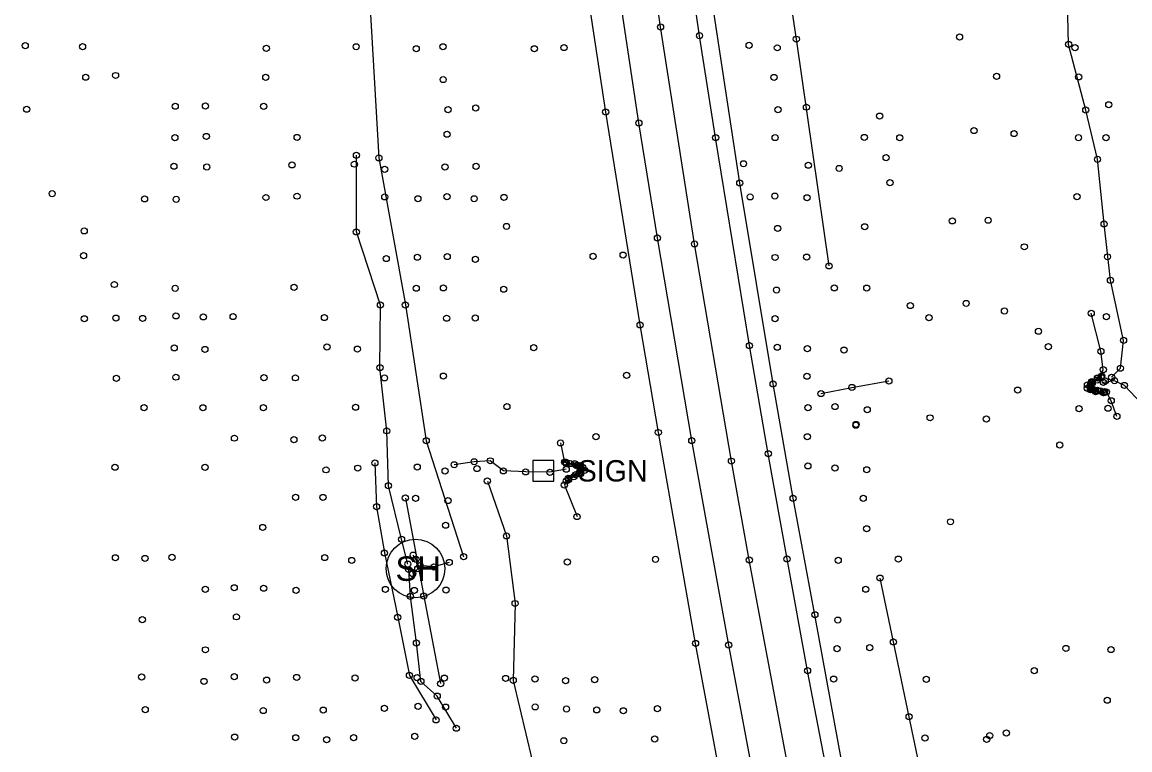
# Model space of a CAD drawing. Extents: x 20503438 to 20508873, y 7964251 to 7984667.
# Drawn here: x 20505289.4 to 20505651.7, y 7977511.9 to 7977750 of the extents above; entities that cross this region are included whole.
import ezdxf

# ---------------------------------------------------------------- set-up
doc = ezdxf.new("R2010")
doc.units = 0
for name, color, linetype in [('SurBreakLine', 7, 'Continuous'), ('SurConcreteSlab', 7, 'Continuous'), ('SurDikeDam', 7, 'Continuous'), ('SurDrainageArrowDown', 7, 'Continuous'), ('SurDrainageArrowUp', 7, 'Continuous'), ('SurEdgeRoadPaved', 7, 'Continuous'), ('SurEdgeShoulderPaved', 7, 'Continuous'), ('SurFenceWire', 7, 'Continuous'), ('SurNaturalCells', 7, 'Continuous'), ('SurPointsNonDTM', 7, 'Continuous'), ('SurRoadPoints', 7, 'Continuous'), ('SurSurveyPoints', 7, 'Continuous')]:
    doc.layers.add(name, color=color, linetype=linetype)

msp = doc.modelspace()

# ---------------------------------------------------------------- linework, layer by layer
at = {"layer": 'SurBreakLine'}
for points in [[(20505621, 7977152.86), (20505604.98, 7977215.01), (20505590.31, 7977274.51), (20505563.53, 7977392.87), (20505556.63, 7977425.21), (20505550.12, 7977454.94), (20505544.87, 7977479.94), (20505527.25, 7977573.99), (20505521.39, 7977606.33), (20505509.32, 7977677.42), (20505498.21, 7977748.43), (20505483.28, 7977852.68), (20505478.77, 7977888.4), (20505466.7, 7977991.92), (20505463.05, 7978027.55)], [(20505647.47, 7977620.99), (20505645.62, 7977626.09), (20505644.06, 7977628.96), (20505643.01, 7977628.73), (20505640.51, 7977629.08), (20505638.82, 7977629.74), (20505637.81, 7977630.2), (20505637.84, 7977631.3), (20505639.26, 7977632.34), (20505641.12, 7977633.5), (20505642.49, 7977634.2), (20505643.03, 7977636.27), (20505642.26, 7977642.28), (20505639.09, 7977654.7)], [(20505465.49, 7977612.31), (20505466.84, 7977606.05), (20505467.31, 7977605.99), (20505470.16, 7977605.47), (20505472.04, 7977604.9), (20505472.78, 7977604.33), (20505473.39, 7977603.28), (20505472.04, 7977602.24), (20505468.21, 7977600.3), (20505467.4, 7977599.82), (20505466.76, 7977598.5), (20505470.9, 7977588.19)], [(20505404.8, 7977605.75), (20505405.32, 7977591.43), (20505407.9, 7977576.32), (20505412.25, 7977555.25), (20505416.09, 7977536.21), (20505424.81, 7977521.66)], [(20505417.14, 7977569.55), (20505418.82, 7977571.12), (20505418.23, 7977574.18), (20505417.3, 7977575.6)], [(20505429.11, 7977573.2), (20505424.11, 7977571.71), (20505419.51, 7977572.18)]]:
    msp.add_lwpolyline(points, dxfattribs=at)
at = {"layer": 'SurConcreteSlab'}
for points in [[(20505643.39, 7977629.05), (20505643.23, 7977628.73), (20505640.36, 7977629.38), (20505639.46, 7977629.72), (20505638.96, 7977630.23), (20505638.77, 7977630.71), (20505638.85, 7977631.5), (20505639.32, 7977632.11), (20505642.33, 7977633.87), (20505642.48, 7977633.61), (20505641.03, 7977632.86), (20505639.43, 7977631.95), (20505639.01, 7977631.33), (20505638.99, 7977631.06), (20505639.01, 7977630.36), (20505639.67, 7977629.84), (20505641.1, 7977629.49), (20505642.12, 7977629.27)], [(20505467.42, 7977605.48), (20505470.56, 7977604.91), (20505471.47, 7977604.61), (20505471.85, 7977604.25), (20505472.06, 7977603.44), (20505471.76, 7977602.7), (20505470.5, 7977601.95), (20505468.03, 7977600.74), (20505468.21, 7977600.4), (20505469.86, 7977601.22), (20505471.5, 7977602.34), (20505472.03, 7977602.74), (20505472.16, 7977603.41), (20505472.05, 7977604.07), (20505471.79, 7977604.59), (20505471.13, 7977604.99), (20505468.69, 7977605.54), (20505467.33, 7977605.79)]]:
    msp.add_lwpolyline(points, close=True, dxfattribs=at)
at = {"layer": 'SurDikeDam'}
msp.add_lwpolyline([(20505550.69, 7977628.45), (20505560.79, 7977630.46), (20505572.91, 7977632.56)], dxfattribs=at)
at = {"layer": 'SurDrainageArrowDown'}
for points in [[(20505397.06, 7977881.61), (20505401.42, 7977854.15), (20505399.21, 7977831.29), (20505394.68, 7977816.75), (20505398.07, 7977791.52), (20505403.18, 7977756.31), (20505406.08, 7977705.57), (20505414.75, 7977657.44), (20505421.59, 7977613), (20505433.78, 7977575.08)], [(20505748.21, 7977193.29), (20505742.63, 7977213.06), (20505736.52, 7977234.9), (20505725.99, 7977280.52), (20505713.88, 7977327.5), (20505706.79, 7977347.37), (20505703.26, 7977372.92), (20505698.22, 7977399.33), (20505687.89, 7977446.43), (20505678.89, 7977496.64), (20505669.89, 7977547.69), (20505664.57, 7977573.19), (20505657.6, 7977599.18), (20505657.57, 7977623.02), (20505649.94, 7977631.12), (20505646.7, 7977632.62), (20505643.09, 7977632.08)], [(20505467.36, 7977603.7), (20505462.05, 7977602.69), (20505454.1, 7977602.82), (20505446.83, 7977603.14), (20505442.51, 7977606.44), (20505437.25, 7977606.12), (20505430.71, 7977605.14)], [(20505431.43, 7977518.95), (20505425.16, 7977529.46), (20505419.84, 7977534.25), (20505418.36, 7977546.85), (20505416.39, 7977562.07), (20505415.84, 7977570.88)], [(20505643.24, 7977229.57), (20505637.82, 7977253.97), (20505632.4, 7977278.37), (20505626.97, 7977302.78), (20505621.55, 7977327.18), (20505616.12, 7977351.59), (20505610.7, 7977375.99), (20505605.27, 7977400.4), (20505600.04, 7977424.84), (20505594.91, 7977449.31), (20505589.78, 7977473.78), (20505584.65, 7977498.25), (20505579.51, 7977522.71), (20505574.38, 7977547.18), (20505570, 7977568.06)]]:
    msp.add_lwpolyline(points, dxfattribs=at)
at = {"layer": 'SurDrainageArrowUp'}
for points in [[(20505474.88, 7978262.46), (20505478.99, 7978261.36), (20505482.21, 7978256.52), (20505486.17, 7978242.38), (20505487.91, 7978215.78), (20505489.93, 7978188.71), (20505495.31, 7978138.74), (20505498.58, 7978086.73), (20505503.22, 7978036.77), (20505509.44, 7977986.63), (20505514.32, 7977937.98), (20505520.92, 7977890), (20505527.82, 7977841.73), (20505542.62, 7977744.41), (20505553.31, 7977670.21)], [(20505645.76, 7977633.8), (20505648.64, 7977636.75), (20505649.66, 7977645.85), (20505645.38, 7977665.53), (20505643.3, 7977683.97), (20505641.13, 7977705.1), (20505637.29, 7977721.21), (20505631.69, 7977742.67), (20505631.11, 7977766.07), (20505627.11, 7977793.04), (20505625.06, 7977817.31), (20505619.53, 7977842.17), (20505617.3, 7977864.92), (20505613.95, 7977892.53), (20505608.5, 7977918.86), (20505604.09, 7977945.74), (20505602.24, 7977974.48), (20505599.16, 7977998.23)], [(20505415.56, 7977572.66), (20505413.52, 7977580.76), (20505409.22, 7977598.28), (20505408.68, 7977616.25), (20505406.45, 7977636.92), (20505406.61, 7977657.41), (20505398.72, 7977681.34), (20505398.75, 7977706.42)], [(20505441.58, 7977599.83), (20505447.83, 7977581.87), (20505450.65, 7977559.76), (20505450.04, 7977534.57), (20505456.22, 7977508.44), (20505457.64, 7977486.03), (20505466.52, 7977459.64), (20505477.85, 7977428.39), (20505482.66, 7977408.47), (20505486.85, 7977381.17), (20505484.36, 7977356.21), (20505484.49, 7977331.46), (20505490.08, 7977296.7), (20505493.03, 7977278)]]:
    msp.add_lwpolyline(points, dxfattribs=at)
at = {"layer": 'SurEdgeRoadPaved'}
for points in [[(20505624.63, 7977187.2), (20505615.58, 7977223), (20505606.62, 7977259.66), (20505597.81, 7977296.68), (20505589.63, 7977332.14), (20505573.81, 7977402.79), (20505559.4, 7977470.78), (20505552.63, 7977504.94), (20505546.29, 7977537.77), (20505539.58, 7977574.35), (20505533.46, 7977608.75), (20505527.3, 7977644.15), (20505516.24, 7977712.18), (20505510.96, 7977745.54), (20505501.31, 7977811.8), (20505496.38, 7977847.32), (20505492.39, 7977879.09), (20505484.78, 7977942.17), (20505477.37, 7978006.84)], [(20505601.04, 7977184.16), (20505592.64, 7977217.57), (20505583.13, 7977256.03), (20505574.67, 7977291.27), (20505566.25, 7977327.77), (20505557.96, 7977364.71), (20505543.09, 7977432.36), (20505534.48, 7977473.22), (20505527.49, 7977508.89), (20505520.5, 7977546.16), (20505508.44, 7977613.06), (20505497.19, 7977679.37), (20505491.12, 7977717.01), (20505485.69, 7977753.34), (20505476.1, 7977820.74), (20505471.46, 7977854.08), (20505467.12, 7977888.06), (20505463.18, 7977920.65), (20505454.58, 7977996.31)]]:
    msp.add_lwpolyline(points, dxfattribs=at)
at = {"layer": 'SurEdgeShoulderPaved'}
for points in [[(20505601.72, 7977139.15), (20505583.71, 7977209.07), (20505575.33, 7977242.93), (20505565.57, 7977283.29), (20505550.94, 7977346.79), (20505536.84, 7977411.29), (20505530.41, 7977441.51), (20505522.43, 7977478.43), (20505509.67, 7977546.7), (20505497.51, 7977615.71), (20505491.52, 7977650.91), (20505480.28, 7977720.53), (20505474.86, 7977756.43), (20505470.13, 7977789.88), (20505464.4, 7977828.65), (20505459.75, 7977863.94), (20505455.67, 7977897.35), (20505450.99, 7977936.46), (20505443.13, 7978005.6)], [(20505641.05, 7977146.39), (20505623.31, 7977215.43), (20505614.62, 7977249.64), (20505606.42, 7977284.19), (20505597.79, 7977321.49), (20505583.89, 7977382.89), (20505576.25, 7977417.57), (20505568.92, 7977452.29), (20505561.28, 7977487.06), (20505548.69, 7977556.07), (20505541.57, 7977594.18), (20505535.02, 7977631.59), (20505524.12, 7977697.3), (20505514.01, 7977764.14), (20505504.07, 7977833.33), (20505499.51, 7977867.01), (20505491.05, 7977936.71), (20505486.93, 7977972.52), (20505483.11, 7978007.2)]]:
    msp.add_lwpolyline(points, dxfattribs=at)
at = {"layer": 'SurFenceWire'}
msp.add_lwpolyline([(20505414.75, 7977594.26), (20505420.77, 7977562.17), (20505426.29, 7977533.54)], dxfattribs=at)
at = {"layer": 'SurNaturalCells'}
msp.add_circle((20505418.04, 7977571.17), 9.59, dxfattribs=at)
at = {"layer": 'SurPointsNonDTM'}
for centre in [(20505562.17, 7977618.34), (20505414.75, 7977594.26), (20505420.77, 7977562.17), (20505426.29, 7977533.54)]:
    msp.add_circle(centre, 1, dxfattribs=at)
at = {"layer": 'SurRoadPoints'}
msp.add_lwpolyline([(20505459.91, 7977599.74), (20505459.91, 7977599.74), (20505463.34, 7977599.74), (20505463.34, 7977606.6), (20505456.48, 7977606.6), (20505456.48, 7977599.74), (20505459.91, 7977599.74)], dxfattribs=at)
at = {"layer": 'SurSurveyPoints'}
for centre in [(20505498.21, 7977748.43), (20505290.41, 7977742.28), (20505510.96, 7977745.54), (20505527.18, 7977742.37), (20505542.62, 7977744.41), (20505596.02, 7977745.1), (20505631.69, 7977742.67), (20505309.18, 7977741.94), (20505369.29, 7977741.4), (20505398.66, 7977741.93), (20505418.32, 7977741.25), (20505427.06, 7977741.92), (20505456.95, 7977741.25), (20505466.64, 7977741.65), (20505536.37, 7977741.57), (20505633.78, 7977741.62), (20505310.21, 7977731.94), (20505319.97, 7977732.52), (20505369.1, 7977731.92), (20505535.34, 7977731.89), (20505608.11, 7977732.23), (20505634.99, 7977732.07), (20505427.12, 7977731.19), (20505290.9, 7977721.47), (20505339.48, 7977722.47), (20505349.35, 7977722.54), (20505368.41, 7977722.41), (20505428.7, 7977721.32), (20505437.79, 7977721.89), (20505480.28, 7977720.53), (20505536.63, 7977721.32), (20505545.93, 7977722.15), (20505637.29, 7977721.21), (20505644.82, 7977722.95), (20505491.12, 7977717.01), (20505569.88, 7977719.22), (20505428.4, 7977713.29), (20505600.73, 7977714.49), (20505613.86, 7977713.51), (20505339.38, 7977712.16), (20505349.67, 7977712.58), (20505379.34, 7977712.24), (20505516.24, 7977712.18), (20505535.7, 7977712.22), (20505564.86, 7977712.24), (20505576.47, 7977712.14), (20505634.92, 7977712.16), (20505643.93, 7977712.19), (20505398.75, 7977706.42), (20505339.03, 7977702.82), (20505349.81, 7977702.56), (20505377.67, 7977703.26), (20505398.07, 7977703.5), (20505406.08, 7977705.57), (20505427.71, 7977702.57), (20505437.9, 7977702.78), (20505525.35, 7977703.63), (20505546.55, 7977703.16), (20505571.99, 7977705.62), (20505641.13, 7977705.1), (20505408.01, 7977701.83), (20505556.64, 7977702.12), (20505524.12, 7977697.3), (20505573.26, 7977697.46), (20505299.23, 7977693.86), (20505329.44, 7977692.13), (20505339.78, 7977691.99), (20505369.14, 7977692.6), (20505379.32, 7977693.03), (20505408.01, 7977692.81), (20505418.86, 7977692.18), (20505428.36, 7977692.87), (20505437.26, 7977692.19), (20505447, 7977692.62), (20505527.53, 7977692.81), (20505535.6, 7977693.05), (20505546.15, 7977692.5), (20505634.43, 7977692.86), (20505593.67, 7977684.94), (20505605.37, 7977685.15), (20505309.7, 7977681.67), (20505398.72, 7977681.34), (20505447.83, 7977683.14), (20505536.53, 7977682.48), (20505564.98, 7977683.02), (20505643.3, 7977683.97), (20505497.19, 7977679.37), (20505509.32, 7977677.42), (20505309.49, 7977673.58), (20505485.98, 7977673.74), (20505617.19, 7977676.46), (20505408.49, 7977672.62), (20505418.69, 7977673.04), (20505428.45, 7977673.28), (20505437.68, 7977672.36), (20505476.15, 7977673.33), (20505535.68, 7977672.97), (20505546.02, 7977673.11), (20505553.31, 7977670.21), (20505644.41, 7977673.19), (20505319.57, 7977664.13), (20505339.46, 7977662.87), (20505378.37, 7977663.22), (20505418.31, 7977662.9), (20505427.2, 7977663.02), (20505446.93, 7977662.58), (20505555.05, 7977663.01), (20505565.67, 7977662.95), (20505645.38, 7977665.53), (20505536.14, 7977662.3), (20505406.61, 7977657.41), (20505414.75, 7977657.44), (20505579.9, 7977657.23), (20505598.18, 7977657.94), (20505610.71, 7977655.46), (20505309.76, 7977652.93), (20505320.07, 7977653.14), (20505328.82, 7977653.02), (20505339.73, 7977653.87), (20505348.66, 7977653.54), (20505358.4, 7977653.65), (20505388.29, 7977653.32), (20505428.26, 7977653.11), (20505437.6, 7977653.17), (20505535.69, 7977652.94), (20505586.02, 7977653.29), (20505639.09, 7977654.7), (20505644.06, 7977653.62), (20505491.52, 7977650.91), (20505621.83, 7977648.85), (20505649.66, 7977645.85), (20505339.15, 7977643.39), (20505349.19, 7977642.9), (20505389.11, 7977643.68), (20505399.07, 7977642.98), (20505456.75, 7977643.45), (20505527.3, 7977644.15), (20505536.37, 7977643.61), (20505546.23, 7977643.12), (20505558.21, 7977642.66), (20505625.07, 7977643.81), (20505642.26, 7977642.28), (20505339.7, 7977633.81), (20505368.5, 7977633.65), (20505378.79, 7977633.59), (20505406.45, 7977636.92), (20505407.93, 7977633.58), (20505427.19, 7977634.15), (20505487.13, 7977634.41), (20505546.11, 7977634.13), (20505642.33, 7977633.87), (20505642.48, 7977633.61), (20505642.49, 7977634.2), (20505643.03, 7977636.27), (20505645.76, 7977633.8), (20505648.64, 7977636.75), (20505320.26, 7977633.42), (20505535.02, 7977631.59), (20505560.79, 7977630.46), (20505572.91, 7977632.56), (20505637.81, 7977630.2), (20505637.84, 7977631.3), (20505638.77, 7977630.71), (20505638.85, 7977631.5), (20505638.96, 7977630.23), (20505638.99, 7977631.06), (20505639.01, 7977631.33), (20505639.01, 7977630.36), (20505639.26, 7977632.34), (20505639.32, 7977632.11), (20505639.43, 7977631.95), (20505641.03, 7977632.86), (20505641.12, 7977633.5), (20505643.09, 7977632.08), (20505643.66, 7977632.6), (20505646.7, 7977632.62), (20505649.94, 7977631.12), (20505550.69, 7977628.45), (20505615.01, 7977629.59), (20505638.82, 7977629.74), (20505639.46, 7977629.72), (20505639.67, 7977629.84), (20505640.36, 7977629.38), (20505640.51, 7977629.08), (20505641.1, 7977629.49), (20505642.12, 7977629.27), (20505643.01, 7977628.73), (20505643.23, 7977628.73), (20505643.39, 7977629.05), (20505644.06, 7977628.96), (20505329.3, 7977623.82), (20505348.54, 7977623.8), (20505368.32, 7977623.83), (20505398.47, 7977623.98), (20505447.96, 7977624.18), (20505546.43, 7977623.84), (20505555.29, 7977624.19), (20505565.82, 7977623.15), (20505635.12, 7977623.52), (20505644.56, 7977623.65), (20505645.62, 7977626.09), (20505586.37, 7977620.51), (20505604.78, 7977620.13), (20505647.47, 7977620.99), (20505408.68, 7977616.25), (20505497.51, 7977615.71), (20505562.09, 7977618.09), (20505358.85, 7977613.85), (20505378.29, 7977613.36), (20505387.58, 7977613.91), (20505421.59, 7977613), (20505465.49, 7977612.31), (20505477.1, 7977614.36), (20505508.44, 7977613.06), (20505546.21, 7977614.31), (20505533.46, 7977608.75), (20505628.78, 7977611.61), (20505404.8, 7977605.75), (20505430.71, 7977605.14), (20505437.25, 7977606.12), (20505442.51, 7977606.44), (20505466.84, 7977606.05), (20505467.31, 7977605.99), (20505467.33, 7977605.79), (20505467.42, 7977605.48), (20505468.69, 7977605.54), (20505470.16, 7977605.47), (20505470.56, 7977604.91), (20505471.13, 7977604.99), (20505471.47, 7977604.61), (20505471.79, 7977604.59), (20505472.04, 7977604.9), (20505521.39, 7977606.33), (20505546.4, 7977604.78), (20505319.76, 7977604.33), (20505349.23, 7977604.31), (20505388.81, 7977603.49), (20505399.19, 7977604.04), (20505418.63, 7977604.38), (20505427.74, 7977603.1), (20505438.17, 7977603.92), (20505446.83, 7977603.14), (20505454.1, 7977602.82), (20505462.05, 7977602.69), (20505467.36, 7977603.7), (20505469.86, 7977601.22), (20505470.5, 7977601.95), (20505471.5, 7977602.34), (20505471.76, 7977602.7), (20505471.85, 7977604.25), (20505472.03, 7977602.74), (20505472.04, 7977602.24), (20505472.05, 7977604.07), (20505472.06, 7977603.44), (20505472.16, 7977603.41), (20505472.78, 7977604.33), (20505473.39, 7977603.28), (20505555.27, 7977604.1), (20505565.68, 7977603.51), (20505409.22, 7977598.28), (20505441.58, 7977599.83), (20505466.76, 7977598.5), (20505467.4, 7977599.82), (20505468.03, 7977600.74), (20505468.21, 7977600.4), (20505468.21, 7977600.3), (20505378.83, 7977594.5), (20505387.81, 7977594.45), (20505418.08, 7977594.18), (20505541.57, 7977594.18), (20505564.51, 7977594.16), (20505405.32, 7977591.43), (20505428.69, 7977593.45), (20505470.9, 7977588.19), (20505593.05, 7977586.48), (20505368.12, 7977584.65), (20505427.89, 7977585.37), (20505565.63, 7977584.22), (20505413.52, 7977580.76), (20505447.83, 7977581.87), (20505407.9, 7977576.32), (20505417.3, 7977575.6), (20505319.93, 7977574.73), (20505329.58, 7977574.5), (20505338.43, 7977574.88), (20505388.4, 7977574.79), (20505397.21, 7977573.84), (20505415.56, 7977572.66), (20505418.23, 7977574.18), (20505419.51, 7977572.18), (20505429.11, 7977573.2), (20505433.78, 7977575.08), (20505467.73, 7977573.35), (20505496.57, 7977574.21), (20505527.25, 7977573.99), (20505539.58, 7977574.35), (20505556.34, 7977573.89), (20505576.01, 7977574.27), (20505415.84, 7977570.88), (20505417.14, 7977569.55), (20505418.82, 7977571.12), (20505424.11, 7977571.71), (20505358.77, 7977564.91), (20505368.4, 7977564.74), (20505570, 7977568.06), (20505349.31, 7977564.39), (20505379.01, 7977564.07), (20505408.22, 7977564.35), (20505416.39, 7977562.07), (20505417.73, 7977564.02), (20505428.06, 7977564.15), (20505565.35, 7977564.43), (20505450.65, 7977559.76), (20505328.71, 7977554.45), (20505359.51, 7977555.39), (20505412.25, 7977555.25), (20505548.69, 7977556.07), (20505556.2, 7977554.33), (20505418.36, 7977546.85), (20505509.67, 7977546.7), (20505574.38, 7977547.18), (20505349.36, 7977544.6), (20505520.5, 7977546.16), (20505555.95, 7977544.97), (20505566.64, 7977545.3), (20505630.81, 7977545.04), (20505645.56, 7977544.68), (20505358.78, 7977535.8), (20505416.09, 7977536.21), (20505546.29, 7977537.77), (20505620.43, 7977537.78), (20505328.49, 7977535.69), (20505348.88, 7977534.26), (20505369.36, 7977534.69), (20505379.21, 7977535.56), (20505398.31, 7977535.38), (20505418.6, 7977535.49), (20505419.84, 7977534.25), (20505427.52, 7977535.35), (20505447.52, 7977535.23), (20505450.04, 7977534.57), (20505457.15, 7977535.04), (20505467.16, 7977534.5), (20505476.65, 7977534.84), (20505554.83, 7977535.01), (20505585.13, 7977534.95), (20505425.16, 7977529.46), (20505329.68, 7977525.03), (20505387.9, 7977524.88), (20505407.9, 7977525.45), (20505418.93, 7977526.11), (20505427.9, 7977525.87), (20505457.21, 7977525.94), (20505467.46, 7977525.23), (20505477.35, 7977524.95), (20505497.21, 7977525.34), (20505644.31, 7977528.11), (20505368.25, 7977524.74), (20505424.81, 7977521.66), (20505486.05, 7977524.65), (20505579.51, 7977522.71), (20505431.43, 7977518.95), (20505358.93, 7977516.03), (20505378.9, 7977515.83), (20505389.01, 7977515.16), (20505397.81, 7977515.84), (20505417.83, 7977516.29), (20505466.58, 7977514.85), (20505496.31, 7977515.41), (20505584.7, 7977515.75), (20505604.88, 7977515.28), (20505605.9, 7977516.56), (20505611.32, 7977517.4)]:
    msp.add_circle(centre, 1, dxfattribs=at)

# ---------------------------------------------------------------- texts
at = {"layer": 'SurNaturalCells'}
msp.add_text('SH', height=7.995, rotation=360, dxfattribs=at).set_placement((20505411.52, 7977567.17))
at = {"layer": 'SurRoadPoints'}
msp.add_text('SIGN', height=6.995, rotation=360, dxfattribs=at).set_placement((20505471.12, 7977599.67))

doc.saveas('drawing.dxf')
